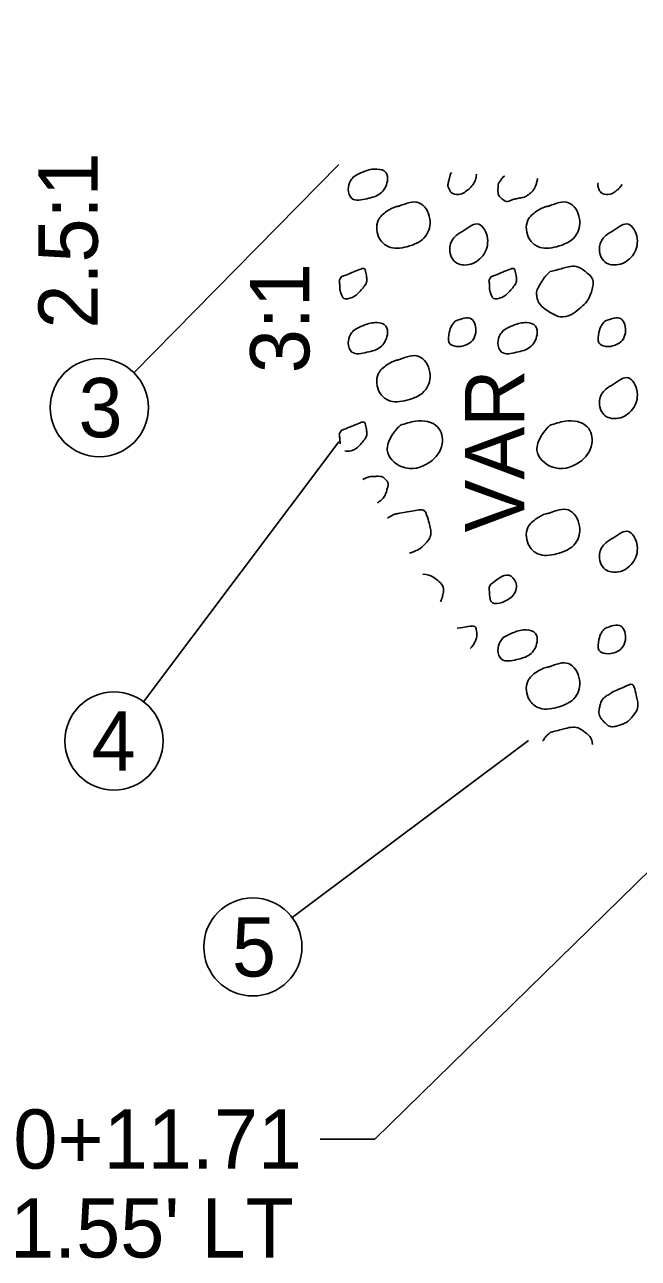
# Model space of a CAD drawing. Extents: x -1577 to 2037, y 0 to 220.
# Drawn here: x 62.56 to 77.06, y 121.06 to 150.21 of the extents above; entities that cross this region are included whole.
import ezdxf

# ---------------------------------------------------------------- set-up
doc = ezdxf.new("R2010")
doc.units = 0
doc.layers.add('GE_P_Alignment_100_Stations', color=7, linetype='Continuous')
doc.layers.add('XS_P_Pavt_Surface', color=7, linetype='Continuous')

msp = doc.modelspace()

# ---------------------------------------------------------------- linework, layer by layer
at = {"layer": 'GE_P_Alignment_100_Stations'}
for p, q in [((97.737, 150.211), (70.83, 123.877)), ((65.14, 141.987), (69.987, 146.904)), ((65.368, 134.21), (69.987, 140.351)), ((68.879, 129.113), (74.46, 133.297)), ((70.83, 123.877), (69.545, 123.877))]:
    msp.add_line(p, q, dxfattribs=at)
for centre in [(64.326, 141.161), (64.671, 133.283), (67.952, 128.417)]:
    msp.add_circle(centre, 1.16, dxfattribs=at)
at = {"layer": 'XS_P_Pavt_Surface'}
for points in [[(70.333, 146.617), (70.583, 146.742), (70.884, 146.799), (71.095, 146.718), (71.129, 146.515), (70.958, 146.218), (70.645, 146.098), (70.293, 146.104), (70.207, 146.32), (70.259, 146.52), (70.333, 146.617)], [(71.42, 145.927), (71.874, 146.003), (72.133, 145.623), (72.036, 145.217), (71.59, 144.964), (71.15, 144.967), (70.951, 145.145), (70.915, 145.59), (71.12, 145.803), (71.345, 145.912), (71.428, 145.929)], [(74.955, 145.927), (75.41, 146.003), (75.669, 145.623), (75.572, 145.217), (75.126, 144.964), (74.686, 144.967), (74.487, 145.145), (74.45, 145.59), (74.655, 145.803), (74.881, 145.912), (74.964, 145.929)], [(72.935, 145.345), (73.287, 145.496), (73.495, 145.157), (73.383, 144.752), (73.05, 144.54), (72.739, 144.599), (72.605, 144.958), (72.751, 145.226), (72.935, 145.345)], [(76.471, 145.345), (76.823, 145.496), (77.03, 145.157), (76.919, 144.752), (76.585, 144.54), (76.275, 144.599), (76.141, 144.958), (76.287, 145.226), (76.471, 145.345)], [(70.333, 142.986), (70.583, 143.111), (70.884, 143.169), (71.095, 143.088), (71.129, 142.884), (70.958, 142.588), (70.645, 142.468), (70.293, 142.474), (70.207, 142.689), (70.259, 142.889), (70.333, 142.986)], [(72.731, 143.203), (73.113, 143.259), (73.217, 142.93), (72.977, 142.636), (72.59, 142.693), (72.593, 142.939), (72.651, 143.102), (72.731, 143.203)], [(73.869, 142.986), (74.119, 143.111), (74.42, 143.169), (74.63, 143.088), (74.665, 142.884), (74.494, 142.588), (74.18, 142.468), (73.829, 142.474), (73.743, 142.689), (73.795, 142.889), (73.869, 142.986)], [(76.267, 143.203), (76.649, 143.259), (76.753, 142.93), (76.513, 142.636), (76.126, 142.693), (76.129, 142.939), (76.187, 143.102), (76.267, 143.203)], [(71.42, 142.297), (71.874, 142.373), (72.133, 141.993), (72.036, 141.586), (71.59, 141.334), (71.15, 141.336), (70.951, 141.514), (70.915, 141.959), (71.12, 142.173), (71.345, 142.281), (71.428, 142.299)], [(76.471, 141.714), (76.823, 141.865), (77.03, 141.527), (76.919, 141.122), (76.585, 140.909), (76.275, 140.969), (76.141, 141.328), (76.287, 141.595), (76.471, 141.714)], [(71.44, 140.745), (71.796, 140.839), (72.317, 140.707), (72.425, 140.304), (72.129, 139.869), (71.48, 139.759), (71.126, 140.157), (71.221, 140.475), (71.36, 140.668), (71.44, 140.745)], [(74.976, 140.745), (75.332, 140.839), (75.853, 140.707), (75.96, 140.304), (75.665, 139.869), (75.016, 139.759), (74.662, 140.157), (74.757, 140.475), (74.895, 140.668), (74.976, 140.745)], [(74.955, 138.666), (75.41, 138.742), (75.669, 138.362), (75.572, 137.956), (75.126, 137.703), (74.686, 137.706), (74.487, 137.884), (74.45, 138.329), (74.655, 138.542), (74.881, 138.651), (74.964, 138.668)], [(76.471, 138.084), (76.823, 138.235), (77.03, 137.896), (76.919, 137.491), (76.585, 137.279), (76.275, 137.338), (76.141, 137.697), (76.287, 137.965), (76.471, 138.084)], [(73.577, 136.989), (74.052, 137.181), (74.178, 136.963), (74.029, 136.661), (73.579, 136.576), (73.54, 136.816), (73.544, 136.937), (73.577, 136.989)], [(73.869, 135.725), (74.119, 135.85), (74.42, 135.908), (74.63, 135.827), (74.665, 135.623), (74.494, 135.327), (74.18, 135.207), (73.829, 135.213), (73.743, 135.428), (73.795, 135.628), (73.869, 135.725)], [(76.267, 135.942), (76.649, 135.998), (76.753, 135.669), (76.513, 135.375), (76.126, 135.432), (76.129, 135.678), (76.187, 135.841), (76.267, 135.942)], [(74.955, 135.036), (75.41, 135.112), (75.669, 134.732), (75.572, 134.325), (75.126, 134.073), (74.686, 134.075), (74.487, 134.253), (74.45, 134.698), (74.655, 134.912), (74.881, 135.02), (74.964, 135.038)]]:
    msp.add_spline(points, degree=3, dxfattribs=at)
for points, degree in [([(73.232, 146.675), (73.233, 146.631), (73.228, 146.59), (73.217, 146.561), (73.178, 146.452), (73.079, 146.344), (72.977, 146.267), (72.872, 146.186), (72.651, 146.2), (72.59, 146.323), (72.552, 146.401), (72.571, 146.491), (72.593, 146.569), (72.607, 146.618), (72.614, 146.674), (72.641, 146.717)], 3), ([(74.676, 146.573), (74.674, 146.553), (74.67, 146.533), (74.665, 146.515), (74.635, 146.41), (74.596, 146.303), (74.494, 146.218), (74.394, 146.135), (74.288, 146.123), (74.18, 146.098), (74.068, 146.072), (73.939, 146.005), (73.829, 146.104), (73.756, 146.169), (73.741, 146.245), (73.743, 146.32), (73.745, 146.386), (73.753, 146.464), (73.795, 146.52), (73.819, 146.553), (73.844, 146.584), (73.869, 146.617)], 3), ([(73.869, 146.617), (73.877, 146.621), (73.885, 146.625), (73.893, 146.629)], 2), ([(76.68, 146.432), (76.634, 146.37), (76.574, 146.313), (76.513, 146.267), (76.408, 146.186), (76.187, 146.2), (76.126, 146.323), (76.103, 146.37), (76.101, 146.422), (76.108, 146.472)], 3), ([(70.041, 144.25), (70.2, 144.314), (70.358, 144.382), (70.516, 144.442), (70.594, 144.472), (70.635, 144.298), (70.642, 144.224), (70.652, 144.124), (70.575, 144.02), (70.493, 143.922), (70.381, 143.787), (70.101, 143.69), (70.043, 143.837), (70.012, 143.916), (70.007, 143.996), (70.004, 144.077), (70.002, 144.118), (69.987, 144.162), (70.008, 144.198), (70.019, 144.216), (70.03, 144.233), (70.041, 144.25)], 3), ([(73.577, 144.25), (73.736, 144.314), (73.894, 144.382), (74.052, 144.442), (74.13, 144.472), (74.171, 144.298), (74.178, 144.224), (74.187, 144.124), (74.111, 144.02), (74.029, 143.922), (73.917, 143.787), (73.637, 143.69), (73.579, 143.837), (73.548, 143.916), (73.543, 143.996), (73.54, 144.077), (73.538, 144.118), (73.523, 144.162), (73.544, 144.198), (73.554, 144.216), (73.566, 144.233), (73.577, 144.25)], 3), ([(74.976, 144.376), (75.095, 144.407), (75.214, 144.438), (75.332, 144.469), (75.505, 144.514), (75.68, 144.482), (75.853, 144.337), (75.987, 144.225), (75.996, 144.059), (75.96, 143.935), (75.916, 143.778), (75.817, 143.63), (75.665, 143.5), (75.475, 143.338), (75.211, 143.274), (75.016, 143.389), (74.859, 143.482), (74.693, 143.622), (74.662, 143.787), (74.643, 143.89), (74.697, 144.01), (74.757, 144.106), (74.8, 144.174), (74.839, 144.243), (74.895, 144.298), (74.922, 144.324), (74.949, 144.35), (74.976, 144.376)], 3), ([(70.041, 140.619), (70.2, 140.683), (70.358, 140.752), (70.516, 140.812), (70.594, 140.842), (70.635, 140.668), (70.642, 140.594), (70.652, 140.494), (70.575, 140.39), (70.493, 140.291), (70.409, 140.19), (70.23, 140.11), (70.121, 140.139)], 3), ([(70.016, 140.305), (70.008, 140.352), (70.006, 140.399), (70.004, 140.447), (70.002, 140.487), (69.987, 140.532), (70.008, 140.568), (70.019, 140.586), (70.03, 140.602), (70.041, 140.619)], 3), ([(70.55, 139.464), (70.561, 139.469), (70.572, 139.475), (70.583, 139.481), (70.675, 139.526), (70.784, 139.535), (70.884, 139.538), (70.957, 139.54), (71.028, 139.523), (71.095, 139.457), (71.155, 139.397), (71.147, 139.317), (71.129, 139.254), (71.099, 139.149), (71.06, 139.042), (70.958, 138.957), (70.938, 138.941), (70.918, 138.927), (70.897, 138.915)], 3), ([(71.13, 138.549), (71.2, 138.593), (71.268, 138.634), (71.345, 138.651), (71.373, 138.656), (71.4, 138.662), (71.428, 138.668)], 3), ([(71.42, 138.666), (71.571, 138.692), (71.722, 138.721), (71.874, 138.742), (72.025, 138.763), (72.095, 138.504), (72.133, 138.362), (72.167, 138.233), (72.145, 138.076), (72.036, 137.956), (71.92, 137.827), (71.793, 137.768), (71.654, 137.723)], 3), ([(71.969, 137.226), (72.085, 137.22), (72.201, 137.173), (72.317, 137.076), (72.452, 136.964), (72.46, 136.798), (72.425, 136.674), (72.414, 136.638), (72.401, 136.603), (72.386, 136.568)], 3), ([(72.779, 135.949), (72.89, 135.965), (73.002, 135.983), (73.113, 135.998), (73.227, 136.013), (73.253, 135.768), (73.217, 135.669), (73.192, 135.6), (73.142, 135.53), (73.083, 135.469)], 3), ([(76.471, 134.453), (76.589, 134.504), (76.706, 134.554), (76.823, 134.604), (76.945, 134.656), (77.004, 134.39), (77.03, 134.266), (77.059, 134.135), (77.025, 133.988), (76.919, 133.861), (76.819, 133.741), (76.705, 133.685), (76.585, 133.648), (76.49, 133.619), (76.369, 133.615), (76.275, 133.708), (76.161, 133.82), (76.118, 133.952), (76.141, 134.067), (76.159, 134.158), (76.202, 134.278), (76.287, 134.334), (76.348, 134.375), (76.41, 134.413), (76.471, 134.453)], 3), ([(74.976, 133.484), (75.095, 133.516), (75.214, 133.547), (75.332, 133.578), (75.505, 133.622), (75.68, 133.591), (75.853, 133.446), (75.936, 133.377), (75.971, 133.287), (75.977, 133.199)], 3), ([(74.795, 133.275), (74.825, 133.322), (74.856, 133.368), (74.895, 133.407), (74.922, 133.433), (74.949, 133.459), (74.976, 133.484)], 3)]:
    msp.add_open_spline(points, degree=degree, dxfattribs=at)

# ---------------------------------------------------------------- texts
at = {"layer": 'GE_P_Alignment_100_Stations'}
for s, p in [('2.5:1', (64.287, 143.029)), ('3:1', (69.287, 141.974)), ('VAR', (74.362, 138.211))]:
    msp.add_text(s, height=1.4, rotation=90, dxfattribs=at).set_placement(p)
for s, p in [('3', (63.834, 140.461)), ('4', (64.144, 132.583)), ('5', (67.457, 127.717)), ('STA 20+11.71', (57.092, 123.177)), ("31.55' LT", (61.175, 121.077))]:
    msp.add_text(s, height=1.4, dxfattribs=at).set_placement(p)

doc.saveas('drawing.dxf')
